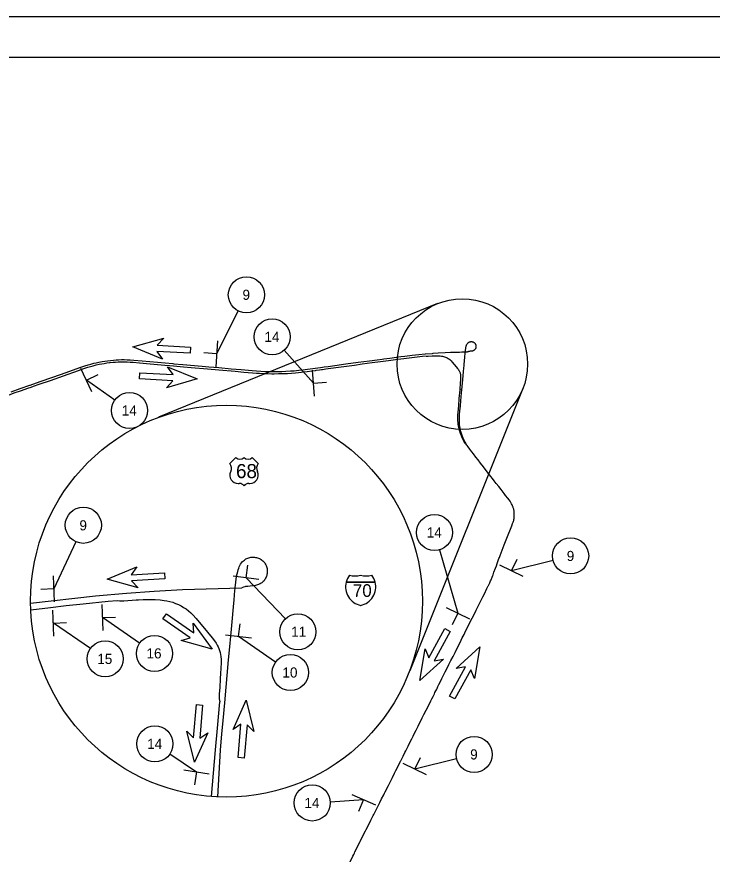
# Model space of a CAD drawing. Extents: x 632.2 to 666.2, y -36.3 to -14.3.
# Drawn here: x 640.6 to 649.19, y -24.64 to -14.3 of the extents above; entities that cross this region are included whole.
import ezdxf

# ---------------------------------------------------------------- set-up
doc = ezdxf.new("R2010")
doc.units = 0
for name, color, linetype in [('Default', 7, 'Continuous'), ('GM_X_County_Subdivision', 7, 'Continuous'), ('GM_X_Township_ROW', 7, 'Continuous'), ('GM_X_Township_Subdivision', 7, 'Continuous'), ('SH_Border', 7, 'Continuous'), ('SH_Cut_Line', 7, 'Continuous'), ('SH_Text', 7, 'Continuous'), ('SN_P_Signs', 7, 'Continuous')]:
    doc.layers.add(name, color=color, linetype=linetype)

msp = doc.modelspace()

# ---------------------------------------------------------------- linework, layer by layer
at = {"layer": 'Default'}
for centre in [(643.436, -17.735), (643.755, -18.254), (641.994, -19.163), (641.423, -20.58), (645.759, -20.669), (647.439, -20.958), (644.072, -21.895), (641.693, -22.229), (642.301, -22.162), (643.979, -22.398), (642.307, -23.279), (646.247, -23.409), (644.249, -24.008)]:
    msp.add_circle(centre, 0.223, dxfattribs=at)
at = {"layer": 'GM_X_County_Subdivision'}
for p, q in [((643.306, -19.745), (643.233, -19.817)), ((643.581, -19.817), (643.509, -19.745)), ((643.335, -20.064), (643.349, -20.064)), ((643.465, -20.064), (643.48, -20.064))]:
    msp.add_line(p, q, dxfattribs=at)
for centre, radius, start, end in [((643.356, -19.693), 0.0725, 225.573, 314.427), ((643.458, -19.693), 0.0725, 225.573, 314.427), ((643.15, -19.875), 0.102, 334.5471, 35.0009), ((643.664, -19.875), 0.102, 144.9991, 205.4529), ((643.334, -19.962), 0.102, 154.8319, 270.6383), ((643.481, -19.962), 0.102, 269.3617, 25.1681), ((643.349, -20.136), 0.0725, 36.8699, 90), ((643.465, -20.136), 0.0725, 90, 143.1301)]:
    msp.add_arc(centre, radius, start, end, dxfattribs=at)
at = {"layer": 'GM_X_Township_ROW'}
for p, q in [((644.666, -21.283), (645.027, -21.283)), ((645.027, -21.283), (644.666, -21.283)), ((645.027, -21.283), (644.666, -21.283))]:
    msp.add_line(p, q, dxfattribs=at)
for centre, start, end in [((644.894, -21.34), 165.8066, 258.463), ((644.894, -21.34), 141.669, 165.8066), ((644.778, -20.971), 253.0091, 286.9909), ((644.915, -20.971), 253.0091, 286.9909), ((644.8, -21.34), 281.537, 14.1934), ((644.8, -21.34), 14.1934, 38.331)]:
    msp.add_arc(centre, 0.234, start, end, dxfattribs=at)
at = {"layer": 'GM_X_Township_Subdivision'}
for p, q in [((642.034, -18.379), (642.416, -18.269)), ((642.416, -18.269), (642.336, -18.358)), ((642.034, -18.379), (642.034, -18.379)), ((642.402, -18.529), (642.034, -18.379)), ((642.336, -18.358), (642.748, -18.38)), ((642.748, -18.38), (642.744, -18.455)), ((642.744, -18.455), (642.332, -18.433)), ((642.332, -18.433), (642.402, -18.529)), ((642.746, -18.417), (642.746, -18.417)), ((642.116, -18.773), (642.12, -18.698)), ((642.12, -18.698), (642.531, -18.72)), ((642.531, -18.72), (642.462, -18.623)), ((642.462, -18.623), (642.829, -18.774)), ((642.527, -18.795), (642.116, -18.773)), ((642.118, -18.735), (642.118, -18.735)), ((642.829, -18.774), (642.448, -18.883)), ((642.448, -18.883), (642.527, -18.795)), ((642.829, -18.774), (642.829, -18.774)), ((641.717, -21.244), (642.085, -21.094)), ((642.085, -21.094), (642.015, -21.19)), ((642.015, -21.19), (642.427, -21.168)), ((642.427, -21.168), (642.431, -21.243)), ((641.717, -21.244), (641.717, -21.244)), ((642.099, -21.354), (641.717, -21.244)), ((642.431, -21.243), (642.019, -21.265)), ((642.019, -21.265), (642.099, -21.354)), ((642.429, -21.205), (642.429, -21.205)), ((642.405, -21.733), (642.448, -21.672)), ((642.427, -21.703), (642.427, -21.703)), ((642.448, -21.672), (642.787, -21.907)), ((642.744, -21.969), (642.405, -21.733)), ((642.787, -21.907), (642.778, -21.788)), ((642.778, -21.788), (643.012, -22.109)), ((645.688, -22.217), (645.886, -21.856)), ((645.952, -21.892), (645.754, -22.253)), ((645.886, -21.856), (645.952, -21.892)), ((645.919, -21.874), (645.919, -21.874)), ((642.63, -22.002), (642.744, -21.969)), ((643.012, -22.109), (642.63, -22.002)), ((643.012, -22.109), (643.012, -22.109)), ((645.577, -22.498), (645.643, -22.107)), ((645.643, -22.107), (645.688, -22.217)), ((646.026, -22.348), (646.32, -22.081)), ((646.32, -22.081), (646.254, -22.473)), ((646.32, -22.081), (646.32, -22.081)), ((645.871, -22.232), (645.577, -22.498)), ((645.754, -22.253), (645.871, -22.232)), ((645.945, -22.688), (646.143, -22.326)), ((646.143, -22.326), (646.026, -22.348)), ((646.209, -22.363), (646.011, -22.724)), ((646.254, -22.473), (646.209, -22.363)), ((645.577, -22.498), (645.577, -22.498)), ((643.271, -23.103), (643.432, -22.741)), ((643.432, -22.741), (643.432, -22.741)), ((643.432, -22.741), (643.53, -23.125)), ((646.011, -22.724), (645.945, -22.688)), ((645.978, -22.706), (645.978, -22.706)), ((642.785, -23.203), (642.82, -22.792)), ((642.82, -22.792), (642.895, -22.799)), ((642.857, -22.796), (642.857, -22.796)), ((642.895, -22.799), (642.86, -23.21)), ((643.369, -23.036), (643.271, -23.103)), ((643.335, -23.447), (643.369, -23.036)), ((643.444, -23.043), (643.409, -23.454)), ((643.53, -23.125), (643.444, -23.043)), ((642.797, -23.506), (642.699, -23.121)), ((642.699, -23.121), (642.785, -23.203)), ((642.959, -23.143), (642.797, -23.506)), ((642.86, -23.21), (642.959, -23.143)), ((643.409, -23.454), (643.335, -23.447)), ((643.372, -23.451), (643.372, -23.451)), ((642.797, -23.506), (642.797, -23.506))]:
    msp.add_line(p, q, dxfattribs=at)
at = {"layer": 'SH_Border'}
msp.add_lwpolyline([(633.687, -14.802), (665.687, -14.802), (665.687, -35.802), (633.687, -35.802)], close=True, dxfattribs=at)
at = {"layer": 'SH_Cut_Line'}
msp.add_lwpolyline([(632.187, -36.302), (666.187, -36.302), (666.187, -14.302), (632.187, -14.302)], close=True, dxfattribs=at)
at = {"layer": 'SH_Text'}
for p, q in [((645.797, -17.844), (642.352, -19.247)), ((643.335, -17.934), (643.069, -18.462)), ((643.903, -18.42), (644.266, -18.827)), ((641.812, -19.034), (641.461, -18.788)), ((646.85, -18.891), (645.452, -22.375)), ((641.329, -20.783), (641.058, -21.365)), ((645.821, -20.883), (646.047, -21.666)), ((647.222, -21.013), (646.708, -21.141)), ((643.918, -21.734), (643.433, -21.229)), ((641.51, -22.102), (641.054, -21.787)), ((642.118, -22.035), (641.661, -21.719)), ((643.795, -22.271), (643.339, -21.955)), ((642.492, -23.403), (642.82, -23.624)), ((646.031, -23.463), (645.516, -23.592)), ((644.472, -23.994), (644.883, -23.967))]:
    msp.add_line(p, q, dxfattribs=at)
for points in [[(646.136, -18.467), (646.145, -18.388), (646.146, -18.385), (646.147, -18.382), (646.149, -18.372), (646.151, -18.365), (646.153, -18.359), (646.155, -18.353), (646.158, -18.347), (646.161, -18.342), (646.164, -18.337), (646.168, -18.332), (646.173, -18.328), (646.176, -18.325), (646.179, -18.323), (646.183, -18.32), (646.187, -18.318), (646.19, -18.317), (646.194, -18.316), (646.198, -18.315), (646.202, -18.314), (646.206, -18.313), (646.21, -18.313), (646.215, -18.313), (646.219, -18.313), (646.223, -18.314), (646.227, -18.315), (646.231, -18.316), (646.235, -18.317), (646.238, -18.319), (646.242, -18.321), (646.245, -18.323), (646.249, -18.325), (646.252, -18.328), (646.255, -18.331), (646.257, -18.334), (646.26, -18.337), (646.262, -18.341), (646.264, -18.344), (646.266, -18.348), (646.267, -18.352), (646.269, -18.356), (646.269, -18.36), (646.27, -18.364), (646.27, -18.368), (646.271, -18.372), (646.27, -18.376), (646.27, -18.38), (646.269, -18.384), (646.268, -18.388), (646.267, -18.392), (646.266, -18.396), (646.264, -18.4), (646.262, -18.403), (646.26, -18.407), (646.257, -18.41), (646.254, -18.413), (646.251, -18.416), (646.248, -18.418), (646.245, -18.421), (646.241, -18.423), (646.238, -18.425), (646.234, -18.426), (646.23, -18.428), (646.226, -18.429), (646.222, -18.43), (646.211, -18.432), (646.2, -18.432), (646.191, -18.433), (646.186, -18.434), (646.182, -18.434), (646.178, -18.435), (646.173, -18.437), (646.165, -18.439)], [(640.533, -18.932), (640.645, -18.893), (640.761, -18.852), (640.767, -18.85), (640.889, -18.807), (641.047, -18.751), (641.21, -18.694), (641.38, -18.634), (641.442, -18.613), (641.481, -18.601), (641.516, -18.59), (641.552, -18.58), (641.58, -18.574), (641.616, -18.566), (641.656, -18.558), (641.688, -18.553), (641.721, -18.548), (641.757, -18.544), (641.794, -18.54), (641.827, -18.538), (641.859, -18.536), (641.896, -18.535), (641.929, -18.535), (641.966, -18.536), (642.002, -18.538), (642.046, -18.542), (642.15, -18.551), (642.526, -18.584), (642.542, -18.586), (642.653, -18.595), (642.891, -18.616), (642.972, -18.623), (643.097, -18.634), (643.25, -18.647), (643.372, -18.658), (643.507, -18.67), (643.561, -18.674), (643.613, -18.678), (643.665, -18.68), (643.719, -18.681), (643.775, -18.682), (643.825, -18.682), (643.875, -18.681), (643.924, -18.679), (643.98, -18.675), (644.026, -18.672), (644.084, -18.667), (644.131, -18.662), (644.189, -18.654), (644.352, -18.632), (644.377, -18.629), (644.396, -18.626), (644.446, -18.619), (644.526, -18.608), (644.665, -18.589), (644.818, -18.568), (644.955, -18.549), (645.051, -18.536), (645.112, -18.528), (645.132, -18.526), (645.205, -18.515), (645.343, -18.497), (645.392, -18.491), (645.481, -18.481), (645.564, -18.472), (645.643, -18.465), (645.649, -18.464), (645.733, -18.458), (645.744, -18.457), (645.805, -18.453), (645.889, -18.448), (645.955, -18.445), (646.066, -18.441), (646.097, -18.44), (646.117, -18.44), (646.139, -18.439), (646.165, -18.439)], [(644.417, -18.65), (644.444, -18.646), (644.608, -18.624), (644.77, -18.602), (644.867, -18.589), (644.99, -18.572), (645.092, -18.558), (645.192, -18.545), (645.306, -18.529), (645.379, -18.52), (645.444, -18.512), (645.645, -18.49)], [(645.653, -18.491), (645.664, -18.492), (645.672, -18.493), (645.681, -18.493), (645.731, -18.489), (645.741, -18.489), (645.76, -18.488), (645.784, -18.488), (645.809, -18.488), (645.83, -18.489), (645.846, -18.491), (645.858, -18.493), (645.87, -18.496), (645.882, -18.499), (645.893, -18.503), (645.905, -18.508), (645.916, -18.513), (645.926, -18.52), (645.937, -18.526), (645.946, -18.534), (645.956, -18.542), (645.964, -18.551), (645.978, -18.566), (646.025, -18.622), (646.044, -18.645), (646.054, -18.658), (646.06, -18.668), (646.065, -18.675), (646.068, -18.682), (646.071, -18.69), (646.074, -18.697), (646.076, -18.705), (646.078, -18.713), (646.079, -18.721), (646.08, -18.734), (646.08, -18.746), (646.079, -18.772), (646.078, -18.791), (646.077, -18.814), (646.075, -18.849), (646.073, -18.876), (646.073, -18.889), (646.073, -18.896), (646.075, -18.908)], [(646.076, -19.138), (646.078, -19.108), (646.084, -19.04), (646.088, -19), (646.093, -18.941), (646.096, -18.912), (646.112, -18.736), (646.117, -18.682), (646.12, -18.639), (646.123, -18.609), (646.125, -18.595), (646.133, -18.503), (646.134, -18.491), (646.136, -18.468)], [(640.418, -19), (640.452, -18.989), (640.498, -18.973), (640.571, -18.947), (640.66, -18.916), (640.738, -18.888), (640.778, -18.875), (640.807, -18.864), (640.877, -18.84), (641.016, -18.791), (641.178, -18.734), (641.364, -18.669), (641.43, -18.646), (641.48, -18.629), (641.512, -18.619), (641.543, -18.61), (641.583, -18.6), (641.619, -18.592), (641.651, -18.586), (641.68, -18.581), (641.712, -18.576), (641.748, -18.572)], [(641.748, -18.572), (641.753, -18.571), (641.79, -18.568), (641.819, -18.565), (641.853, -18.563), (641.895, -18.562), (641.927, -18.562), (641.964, -18.563), (642.001, -18.565), (642.04, -18.568), (642.117, -18.575), (642.248, -18.586), (642.43, -18.603), (642.485, -18.608), (642.538, -18.612), (642.658, -18.623), (642.756, -18.631), (642.955, -18.649), (643.096, -18.661), (643.299, -18.679), (643.406, -18.688), (643.51, -18.697), (643.563, -18.701), (643.598, -18.704), (643.656, -18.706), (643.701, -18.708), (643.749, -18.709), (643.779, -18.709), (643.831, -18.708), (643.881, -18.707), (643.943, -18.705), (643.994, -18.701), (644.043, -18.698), (644.08, -18.694), (644.144, -18.687), (644.188, -18.682), (644.248, -18.674), (644.291, -18.668), (644.299, -18.667)], [(644.299, -18.667), (644.34, -18.661), (644.365, -18.658)], [(644.365, -18.658), (644.374, -18.656), (644.417, -18.65)], [(646.16, -19.596), (646.156, -19.593), (646.152, -19.589), (646.149, -19.584), (646.143, -19.576), (646.136, -19.565), (646.128, -19.554), (646.121, -19.541), (646.109, -19.517), (646.1, -19.499), (646.09, -19.476), (646.08, -19.45), (646.074, -19.43), (646.068, -19.411), (646.063, -19.391), (646.058, -19.371), (646.055, -19.351), (646.052, -19.33), (646.05, -19.31), (646.048, -19.29), (646.047, -19.269), (646.047, -19.245), (646.048, -19.216), (646.05, -19.183), (646.057, -19.106), (646.065, -19.016), (646.075, -18.908)], [(646.16, -19.596), (646.159, -19.591), (646.158, -19.589), (646.155, -19.583), (646.14, -19.559), (646.13, -19.541), (646.121, -19.522), (646.112, -19.503), (646.105, -19.484), (646.096, -19.461), (646.092, -19.449), (646.087, -19.435), (646.084, -19.421), (646.08, -19.405), (646.075, -19.382), (646.072, -19.361), (646.069, -19.34), (646.068, -19.32), (646.067, -19.3), (646.066, -19.277), (646.067, -19.252), (646.069, -19.218), (646.073, -19.169), (646.076, -19.138)], [(646.385, -19.887), (646.362, -19.858), (646.327, -19.812), (646.297, -19.774), (646.27, -19.739), (646.239, -19.699), (646.22, -19.675), (646.194, -19.641), (646.173, -19.613), (646.16, -19.596)], [(646.704, -20.609), (646.713, -20.587), (646.723, -20.56), (646.729, -20.543), (646.733, -20.531), (646.736, -20.519), (646.738, -20.509), (646.741, -20.495), (646.742, -20.484), (646.743, -20.479), (646.744, -20.464), (646.744, -20.451), (646.744, -20.439), (646.742, -20.419), (646.74, -20.402), (646.739, -20.393), (646.737, -20.382), (646.734, -20.372), (646.731, -20.363), (646.729, -20.357), (646.727, -20.351), (646.722, -20.339), (646.716, -20.326), (646.711, -20.316), (646.706, -20.307), (646.701, -20.298), (646.691, -20.283), (646.679, -20.266), (646.663, -20.246), (646.637, -20.212), (646.618, -20.188), (646.582, -20.14), (646.551, -20.101), (646.521, -20.063), (646.496, -20.03), (646.475, -20.003), (646.454, -19.976), (646.425, -19.939), (646.397, -19.902), (646.389, -19.893), (646.385, -19.887)], [(646.278, -21.618), (646.287, -21.602), (646.294, -21.586), (646.306, -21.563), (646.331, -21.513), (646.356, -21.463), (646.374, -21.427), (646.406, -21.361), (646.422, -21.328), (646.425, -21.323), (646.437, -21.299), (646.44, -21.291), (646.441, -21.29), (646.445, -21.28), (646.451, -21.267), (646.456, -21.253), (646.47, -21.219), (646.477, -21.202), (646.481, -21.19), (646.492, -21.16), (646.511, -21.109), (646.522, -21.08), (646.533, -21.05), (646.554, -20.992), (646.559, -20.979), (646.569, -20.953), (646.593, -20.888), (646.607, -20.854), (646.619, -20.822), (646.628, -20.801), (646.66, -20.72), (646.704, -20.609)], [(643.311, -21.217), (643.317, -21.199), (643.32, -21.19), (643.323, -21.18), (643.329, -21.149), (643.336, -21.128), (643.341, -21.11), (643.348, -21.092), (643.355, -21.075), (643.364, -21.06), (643.375, -21.044), (643.388, -21.029), (643.401, -21.017), (643.411, -21.009), (643.42, -21.002), (643.431, -20.995), (643.442, -20.989), (643.453, -20.985), (643.465, -20.981), (643.477, -20.978), (643.489, -20.975), (643.501, -20.974), (643.513, -20.973), (643.526, -20.973), (643.538, -20.974), (643.55, -20.976), (643.562, -20.978), (643.574, -20.981), (643.586, -20.985), (643.597, -20.99), (643.608, -20.996), (643.618, -21.002), (643.628, -21.01), (643.638, -21.018), (643.647, -21.026), (643.655, -21.036), (643.662, -21.045), (643.669, -21.056), (643.675, -21.067), (643.68, -21.077), (643.684, -21.089), (643.688, -21.101), (643.691, -21.113), (643.693, -21.125), (643.694, -21.138), (643.694, -21.15), (643.693, -21.162), (643.692, -21.174), (643.69, -21.187), (643.687, -21.199), (643.684, -21.21), (643.679, -21.222), (643.674, -21.233), (643.668, -21.244), (643.661, -21.254), (643.654, -21.264), (643.645, -21.273), (643.636, -21.281), (643.627, -21.289), (643.617, -21.296), (643.606, -21.302), (643.595, -21.308), (643.585, -21.312), (643.572, -21.317), (643.562, -21.32), (643.548, -21.324), (643.515, -21.329), (643.481, -21.331), (643.456, -21.334), (643.439, -21.335), (643.427, -21.337), (643.416, -21.34), (643.402, -21.344), (643.378, -21.351)], [(643.291, -21.439), (643.291, -21.436), (643.299, -21.352), (643.313, -21.211)], [(640.771, -21.543), (641.574, -21.45), (641.955, -21.417), (642.297, -21.392), (642.649, -21.374), (643.378, -21.351)], [(641.84, -21.507), (641.874, -21.511), (641.898, -21.513), (641.925, -21.512), (642.076, -21.502), (642.105, -21.501), (642.162, -21.498), (642.235, -21.497), (642.309, -21.498), (642.37, -21.502), (642.419, -21.507), (642.456, -21.513), (642.492, -21.521), (642.527, -21.531), (642.562, -21.544), (642.596, -21.558), (642.629, -21.574), (642.661, -21.593), (642.692, -21.613), (642.721, -21.636), (642.749, -21.66), (642.775, -21.686), (642.816, -21.732), (642.958, -21.901), (643.013, -21.968), (643.043, -22.007), (643.063, -22.037), (643.076, -22.058), (643.087, -22.08), (643.096, -22.103), (643.105, -22.126), (643.111, -22.15), (643.117, -22.174), (643.12, -22.198), (643.123, -22.235), (643.123, -22.272), (643.12, -22.349), (643.117, -22.406), (643.113, -22.477), (643.107, -22.582), (643.102, -22.662), (643.101, -22.702), (643.102, -22.722), (643.107, -22.759)], [(643.083, -23.934), (643.117, -23.358), (643.135, -23.155), (643.146, -23.035), (643.162, -22.857), (643.17, -22.77), (643.217, -22.242), (643.232, -22.08), (643.243, -21.95), (643.252, -21.862), (643.256, -21.819), (643.281, -21.542), (643.284, -21.506), (643.291, -21.439)], [(640.774, -21.625), (641.018, -21.593), (641.213, -21.57), (641.421, -21.548), (641.73, -21.517), (641.84, -21.507)], [(645.656, -22.862), (645.695, -22.783), (645.713, -22.747), (645.716, -22.741), (645.726, -22.721), (645.741, -22.692), (645.757, -22.66), (645.764, -22.645), (645.774, -22.625), (645.782, -22.61), (645.79, -22.594), (645.801, -22.572), (645.814, -22.545), (645.832, -22.509), (645.851, -22.472), (645.871, -22.431), (645.892, -22.391), (645.919, -22.336), (645.937, -22.3), (645.962, -22.249), (645.988, -22.198), (646.013, -22.15), (646.044, -22.088), (646.074, -22.027), (646.102, -21.971), (646.123, -21.928), (646.143, -21.889), (646.225, -21.725), (646.251, -21.672), (646.273, -21.629), (646.278, -21.618)], [(643.004, -23.929), (643.054, -23.352), (643.078, -23.083), (643.107, -22.759)], [(645.013, -24.143), (645.044, -24.083), (645.084, -24.003), (645.106, -23.959), (645.132, -23.907), (645.143, -23.886), (645.151, -23.87), (645.164, -23.843), (645.174, -23.823), (645.191, -23.791), (645.202, -23.769), (645.218, -23.736), (645.24, -23.692), (645.265, -23.64), (645.281, -23.608), (645.296, -23.578), (645.311, -23.549), (645.329, -23.513), (645.34, -23.49), (645.343, -23.486), (645.359, -23.454), (645.37, -23.431), (645.393, -23.387), (645.403, -23.366), (645.425, -23.322), (645.429, -23.315), (645.432, -23.307), (645.438, -23.296), (645.479, -23.216), (645.495, -23.183), (645.504, -23.164), (645.532, -23.108), (645.556, -23.061), (645.574, -23.024), (645.595, -22.984), (645.607, -22.959), (645.627, -22.918), (645.655, -22.863), (645.656, -22.862)], [(644.841, -24.484), (644.845, -24.475), (644.871, -24.423), (644.906, -24.354), (644.916, -24.334), (644.954, -24.258), (644.972, -24.222), (644.993, -24.181), (645.003, -24.163), (645.01, -24.149), (645.013, -24.143)], [(644.77, -24.626), (644.776, -24.613), (644.79, -24.584), (644.817, -24.53), (644.841, -24.484)], [(644.677, -24.816), (644.687, -24.794), (644.711, -24.746), (644.732, -24.702), (644.751, -24.663), (644.761, -24.643), (644.77, -24.626)]]:
    msp.add_lwpolyline(points, dxfattribs=at)
for centre, radius in [((646.102, -18.59), 0.806), ((643.19, -21.517), 2.419)]:
    msp.add_circle(centre, radius, dxfattribs=at)
at = {"layer": 'SN_P_Signs'}
for p, q in [((643.08, -18.303), (643.057, -18.622)), ((643.069, -18.462), (642.909, -18.451)), ((641.529, -18.933), (641.394, -18.643)), ((644.277, -18.986), (644.254, -18.667)), ((641.461, -18.788), (641.606, -18.72)), ((644.266, -18.827), (644.425, -18.815)), ((643.433, -21.229), (643.452, -21.071)), ((646.852, -21.212), (646.565, -21.071)), ((646.708, -21.141), (646.779, -20.998)), ((641.051, -21.205), (641.064, -21.524)), ((643.591, -21.249), (643.274, -21.21)), ((641.058, -21.365), (640.898, -21.371)), ((641.668, -21.879), (641.655, -21.56)), ((645.903, -21.596), (646.19, -21.737)), ((641.06, -21.947), (641.047, -21.627)), ((646.047, -21.666), (645.977, -21.81)), ((641.054, -21.787), (641.214, -21.78)), ((641.661, -21.719), (641.821, -21.713)), ((643.339, -21.955), (643.359, -21.797)), ((643.498, -21.975), (643.18, -21.936)), ((645.516, -23.592), (645.587, -23.448)), ((645.66, -23.662), (645.373, -23.521)), ((642.662, -23.6), (642.978, -23.649)), ((642.82, -23.624), (642.796, -23.783)), ((644.737, -23.903), (645.03, -24.031)), ((644.883, -23.967), (644.819, -24.114))]:
    msp.add_line(p, q, dxfattribs=at)

# ---------------------------------------------------------------- texts
at = {"layer": 'Default'}
for s, p in [('9', (643.388, -17.797)), ('14', (643.659, -18.316)), ('14', (641.898, -19.225)), ('9', (641.375, -20.643)), ('14', (645.663, -20.731)), ('9', (647.391, -21.021)), ('11', (643.989, -21.957)), ('16', (642.203, -22.224)), ('15', (641.595, -22.292)), ('10', (643.881, -22.46)), ('14', (642.211, -23.341)), ('9', (646.199, -23.471)), ('14', (644.153, -24.07))]:
    msp.add_text(s, height=0.125, dxfattribs=at).set_placement(p)
at = {"layer": 'GM_X_County_Subdivision'}
msp.add_text('68', height=0.174, dxfattribs=at).set_placement((643.308, -19.998))
at = {"layer": 'GM_X_Township_ROW'}
msp.add_text('70', height=0.1562, dxfattribs=at).set_placement((644.751, -21.464))

doc.saveas('drawing.dxf')
